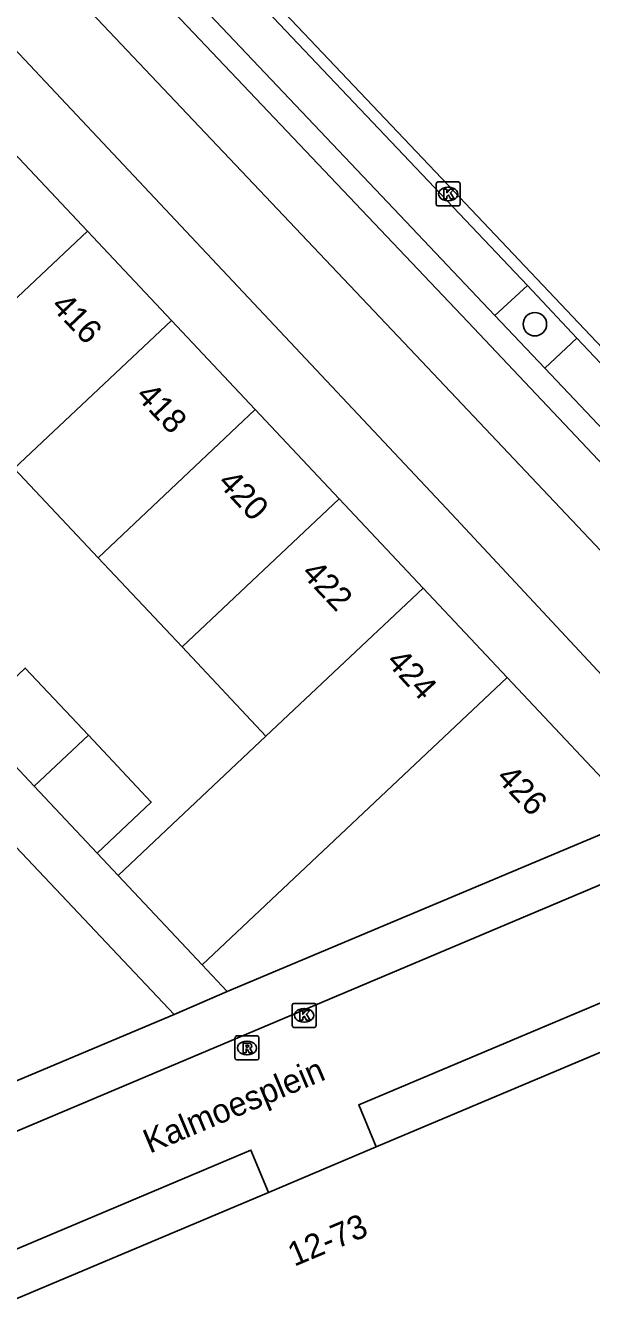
# Model space of a CAD drawing. Extents: x 162542 to 163144, y 380786 to 381511.
# Drawn here: x 163072.1 to 163095.7, y 381233.7 to 381287.3 of the extents above; entities that cross this region are included whole.
import ezdxf

# ---------------------------------------------------------------- set-up
doc = ezdxf.new("R2010")
doc.units = 0
for name, color, linetype in [('IMGEO_Berm_open', 7, 'Continuous'), ('IMGEO_Boom', 7, 'Continuous'), ('IMGEO_Fietspad_gesloten', 7, 'Continuous'), ('IMGEO_Kolk', 7, 'Continuous'), ('IMGEO_Openbare_ruimte_label', 7, 'Continuous'), ('IMGEO_Pand', 7, 'Continuous'), ('IMGEO_Pand_nummerreeks', 7, 'Continuous'), ('IMGEO_Parkeervlak_gesloten', 7, 'Continuous'), ('IMGEO_Parkeervlak_open', 7, 'Continuous'), ('IMGEO_Rijbaan_lokaal_gesloten', 7, 'Continuous'), ('IMGEO_Rijbaan_lokaal_open', 7, 'Continuous'), ('IMGEO_Rioolput', 7, 'Continuous'), ('IMGEO_Voetpad_open', 7, 'Continuous')]:
    doc.layers.add(name, color=color, linetype=linetype)

msp = doc.modelspace()

# ---------------------------------------------------------------- linework, layer by layer
at = {"layer": 'IMGEO_Berm_open'}
msp.add_lwpolyline([(163093.719, 381273.004), (163091.635, 381275.204)], dxfattribs=at)
at = {"layer": 'IMGEO_Boom'}
msp.add_circle((163093.307, 381274.841), 0.489, dxfattribs=at)
at = {"layer": 'IMGEO_Fietspad_gesloten'}
for points in [[(163104.019, 381256.98), (163088.345, 381273.544), (163051.171, 381312.75)], [(163060.553, 381306.481), (163090.503, 381274.946), (163119.19, 381244.596)]]:
    msp.add_lwpolyline(points, dxfattribs=at)
at = {"layer": 'IMGEO_Kolk'}
for p, q in [((163089.264, 381280.771), (163090.116, 381280.771)), ((163089.189, 381279.845), (163089.189, 381280.697)), ((163089.677, 381280.551), (163089.702, 381280.551)), ((163090.19, 381280.697), (163090.19, 381279.845)), ((163090.116, 381279.771), (163089.264, 381279.771)), ((163089.7, 381279.991), (163089.675, 381279.991)), ((163083.254, 381246.519), (163084.106, 381246.519)), ((163083.179, 381245.593), (163083.179, 381246.445)), ((163083.667, 381246.299), (163083.692, 381246.299)), ((163084.18, 381246.445), (163084.18, 381245.593)), ((163084.106, 381245.519), (163083.254, 381245.519)), ((163083.69, 381245.739), (163083.665, 381245.739))]:
    msp.add_line(p, q, dxfattribs=at)
for points in [[(163089.264, 381280.771), (163090.116, 381280.771)], [(163089.189, 381279.845), (163089.189, 381280.697)], [(163089.51, 381280.471), (163089.633, 381280.471), (163089.633, 381280.32), (163089.763, 381280.471), (163089.927, 381280.471), (163089.781, 381280.32), (163089.934, 381280.071), (163089.782, 381280.071), (163089.697, 381280.235), (163089.633, 381280.168), (163089.633, 381280.071), (163089.51, 381280.071), (163089.51, 381280.471)], [(163090.19, 381280.697), (163090.19, 381279.845)], [(163090.116, 381279.771), (163089.264, 381279.771)], [(163083.254, 381246.519), (163084.106, 381246.519)], [(163083.179, 381245.593), (163083.179, 381246.445)], [(163083.5, 381246.219), (163083.623, 381246.219), (163083.623, 381246.068), (163083.753, 381246.219), (163083.917, 381246.219), (163083.771, 381246.068), (163083.924, 381245.819), (163083.772, 381245.819), (163083.687, 381245.983), (163083.623, 381245.916), (163083.623, 381245.819), (163083.5, 381245.819), (163083.5, 381246.219)], [(163084.18, 381246.445), (163084.18, 381245.593)], [(163084.106, 381245.519), (163083.254, 381245.519)]]:
    msp.add_lwpolyline(points, dxfattribs=at)
for centre, start, end in [((163089.266, 381280.695), 91.552, 178.448), ((163089.266, 381280.695), 91.552, 178.448), ((163090.114, 381280.695), 1.552, 88.448), ((163090.114, 381280.695), 1.552, 88.448), ((163089.266, 381279.847), 181.552, 268.448), ((163089.266, 381279.847), 181.552, 268.448), ((163090.114, 381279.847), 271.552, 358.448), ((163090.114, 381279.847), 271.552, 358.448), ((163083.256, 381246.443), 91.552, 178.448), ((163083.256, 381246.443), 91.552, 178.448), ((163084.104, 381246.443), 1.552, 88.448), ((163084.104, 381246.443), 1.552, 88.448), ((163083.256, 381245.595), 181.552, 268.448), ((163083.256, 381245.595), 181.552, 268.448), ((163084.104, 381245.595), 271.552, 358.448), ((163084.104, 381245.595), 271.552, 358.448)]:
    msp.add_arc(centre, 0.0765, start, end, dxfattribs=at)
for centre, major_axis, ratio, start_param, end_param in [((163089.676, 381280.271), (-0.387, 0.002), 0.722429, 4.712389, 7.853982), ((163089.701, 381280.271), (-0.39, 0.002), 0.717154, 1.570796, 4.712389), ((163083.666, 381246.019), (-0.387, 0.002), 0.722429, 4.712389, 7.853982), ((163083.691, 381246.019), (-0.39, 0.002), 0.717154, 1.570796, 4.712389)]:
    msp.add_ellipse(centre, major_axis=major_axis, ratio=ratio, start_param=start_param, end_param=end_param, dxfattribs=at)
at = {"layer": 'IMGEO_Pand'}
for points in [[(163074.636, 381278.72), (163071.133, 381282.441)], [(163074.636, 381278.72), (163068.077, 381272.545)], [(163078.139, 381274.999), (163074.636, 381278.72)], [(163078.139, 381274.999), (163071.579, 381268.824)], [(163081.641, 381271.279), (163078.139, 381274.999)], [(163081.641, 381271.279), (163075.082, 381265.104)], [(163085.144, 381267.558), (163081.641, 381271.279)], [(163075.082, 381265.104), (163071.579, 381268.824)], [(163078.585, 381261.383), (163085.144, 381267.558)], [(163088.646, 381263.837), (163085.144, 381267.558)], [(163078.585, 381261.383), (163075.082, 381265.104)], [(163082.087, 381257.662), (163088.646, 381263.837)], [(163092.152, 381260.113), (163088.646, 381263.837)], [(163082.087, 381257.662), (163078.585, 381261.383)], [(163074.675, 381257.702), (163072.043, 381260.498), (163069.786, 381258.373)], [(163079.421, 381248.129), (163092.152, 381260.113)], [(163097.674, 381254.248), (163092.152, 381260.113)], [(163069.786, 381258.373), (163072.417, 381255.577)], [(163074.675, 381257.702), (163072.417, 381255.577)], [(163075.042, 381252.789), (163077.3, 381254.914), (163074.675, 381257.702)], [(163075.923, 381251.854), (163078.179, 381253.98), (163082.087, 381257.662)], [(163072.417, 381255.577), (163075.042, 381252.789)], [(163080.469, 381247.013), (163097.674, 381254.248)], [(163071.658, 381253.039), (163078.255, 381246.061)], [(163079.421, 381248.129), (163075.923, 381251.854)], [(163080.469, 381247.013), (163079.421, 381248.129)], [(163103.952, 381247.808), (163086.685, 381240.532)], [(163058.261, 381237.648), (163078.255, 381246.061)], [(163086.685, 381240.532), (163082.192, 381238.639)], [(163082.192, 381238.639), (163057.157, 381228.09)]]:
    msp.add_lwpolyline(points, dxfattribs=at)
at = {"layer": 'IMGEO_Parkeervlak_gesloten'}
for points in [[(163092.999, 381276.451), (163080.574, 381289.551)], [(163092.999, 381276.451), (163095.055, 381274.262)], [(163095.055, 381274.262), (163111.541, 381256.861)]]:
    msp.add_lwpolyline(points, dxfattribs=at)
at = {"layer": 'IMGEO_Parkeervlak_open'}
for points in [[(163079.232, 381288.282), (163087.678, 381279.381), (163091.635, 381275.204)], [(163091.635, 381275.204), (163092.999, 381276.451)], [(163093.719, 381273.004), (163095.055, 381274.262)], [(163110.191, 381255.617), (163093.719, 381273.004)]]:
    msp.add_lwpolyline(points, dxfattribs=at)
at = {"layer": 'IMGEO_Rijbaan_lokaal_gesloten'}
msp.add_lwpolyline([(163060.637, 381311.22), (163089.409, 381280.927), (163123.991, 381244.438)], dxfattribs=at)
at = {"layer": 'IMGEO_Rijbaan_lokaal_open'}
for points in [[(163056.729, 381234.882), (163101.329, 381253.703)], [(163103.11, 381249.521), (163085.96, 381242.293), (163086.685, 381240.532)], [(163082.192, 381238.639), (163081.459, 381240.403), (163057.755, 381230.408)]]:
    msp.add_lwpolyline(points, dxfattribs=at)
at = {"layer": 'IMGEO_Rioolput'}
for p, q in [((163080.794, 381244.233), (163080.794, 381245.085)), ((163080.869, 381245.159), (163081.721, 381245.159)), ((163081.282, 381244.939), (163081.307, 381244.939)), ((163081.795, 381245.085), (163081.795, 381244.233)), ((163081.305, 381244.379), (163081.28, 381244.379)), ((163081.721, 381244.159), (163080.869, 381244.159))]:
    msp.add_line(p, q, dxfattribs=at)
for points in [[(163080.794, 381244.233), (163080.794, 381245.085)], [(163080.869, 381245.159), (163081.721, 381245.159)], [(163081.795, 381245.085), (163081.795, 381244.233)], [(163081.383, 381244.857), (163081.131, 381244.859), (163081.131, 381244.459)], [(163081.131, 381244.459), (163081.255, 381244.459), (163081.255, 381244.621), (163081.266, 381244.621)], [(163081.309, 381244.778), (163081.255, 381244.778), (163081.255, 381244.697)], [(163081.255, 381244.697), (163081.307, 381244.697)], [(163081.313, 381244.592), (163081.384, 381244.459), (163081.524, 381244.459), (163081.459, 381244.585)], [(163081.721, 381244.159), (163080.869, 381244.159)]]:
    msp.add_lwpolyline(points, dxfattribs=at)
for centre, radius, start, end in [((163080.871, 381245.083), 0.0765, 91.552, 178.448), ((163080.871, 381245.083), 0.0765, 91.552, 178.448), ((163081.719, 381245.083), 0.0765, 1.552, 88.448), ((163081.719, 381245.083), 0.0765, 1.552, 88.448), ((163081.265, 381244.568), 0.0533, 26.0293, 88.6989), ((163081.291, 381244.886), 0.19, 274.7715, 282.9687), ((163081.315, 381244.682), 0.0964, 77.0061, 93.1865), ((163081.329, 381244.739), 0.0378, 276.6634, 79.6772), ((163081.382, 381244.747), 0.109, 350.3612, 89.416), ((163081.38, 381244.747), 0.112, 277.5842, 350.9817), ((163081.364, 381244.532), 0.108, 29.5134, 73.7905), ((163080.871, 381244.235), 0.0765, 181.552, 268.448), ((163080.871, 381244.235), 0.0765, 181.552, 268.448), ((163081.719, 381244.235), 0.0765, 271.552, 358.448), ((163081.719, 381244.235), 0.0765, 271.552, 358.448)]:
    msp.add_arc(centre, radius, start, end, dxfattribs=at)
for centre, major_axis, ratio, start_param, end_param in [((163081.281, 381244.659), (-0.387, 0.002), 0.722429, 4.712389, 7.853982), ((163081.306, 381244.659), (-0.39, 0.002), 0.717154, 1.570796, 4.712389)]:
    msp.add_ellipse(centre, major_axis=major_axis, ratio=ratio, start_param=start_param, end_param=end_param, dxfattribs=at)
at = {"layer": 'IMGEO_Voetpad_open'}
for points in [[(163059.616, 381299.052), (163089.827, 381266.935), (163100.495, 381255.489)], [(163075.042, 381252.789), (163075.923, 381251.854)], [(163078.255, 381246.061), (163080.469, 381247.013)]]:
    msp.add_lwpolyline(points, dxfattribs=at)

# ---------------------------------------------------------------- texts
at = {"layer": 'IMGEO_Openbare_ruimte_label'}
msp.add_text('Kalmoesplein', height=1, rotation=22.8225, dxfattribs=at).set_placement((163077.234, 381240.249))
at = {"layer": 'IMGEO_Pand_nummerreeks'}
for s, rotation, p in [('416', 313.4306, (163073.073, 381275.563)), ('418', 313.4306, (163076.614, 381271.823)), ('420', 312.9975, (163080.03, 381268.201)), ('422', 313.4306, (163083.522, 381264.42)), ('424', 312.2737, (163087.065, 381260.745)), ('426', 313.4926, (163091.652, 381255.889)), ('12-73', 22.8501, (163083.266, 381235.532))]:
    msp.add_text(s, height=1, rotation=rotation, dxfattribs=at).set_placement(p)

doc.saveas('drawing.dxf')
